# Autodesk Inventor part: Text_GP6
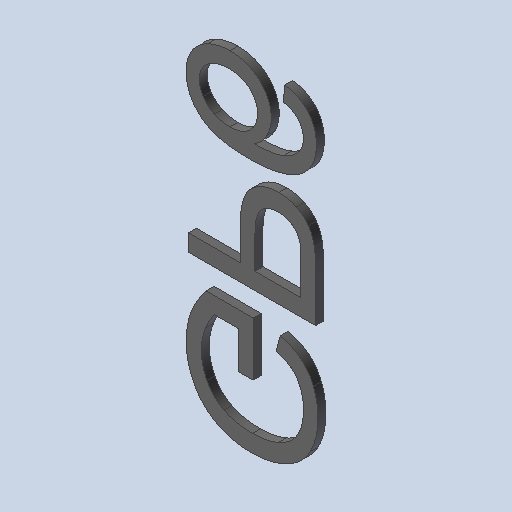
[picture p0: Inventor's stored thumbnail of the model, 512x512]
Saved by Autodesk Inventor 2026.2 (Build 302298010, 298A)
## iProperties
Created: 2026-10
Part Number: Text_GP6
Material: Générique
Document SubType Name: Modeling
Designer: mel
Density: 1 g/cm^3
Appearance: Par défaut
Author: mel
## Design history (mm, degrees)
feature "Base1"
feature "Base2"
feature "Base3"
node "Solide1"
node "Solide2"
node "Solide3"
